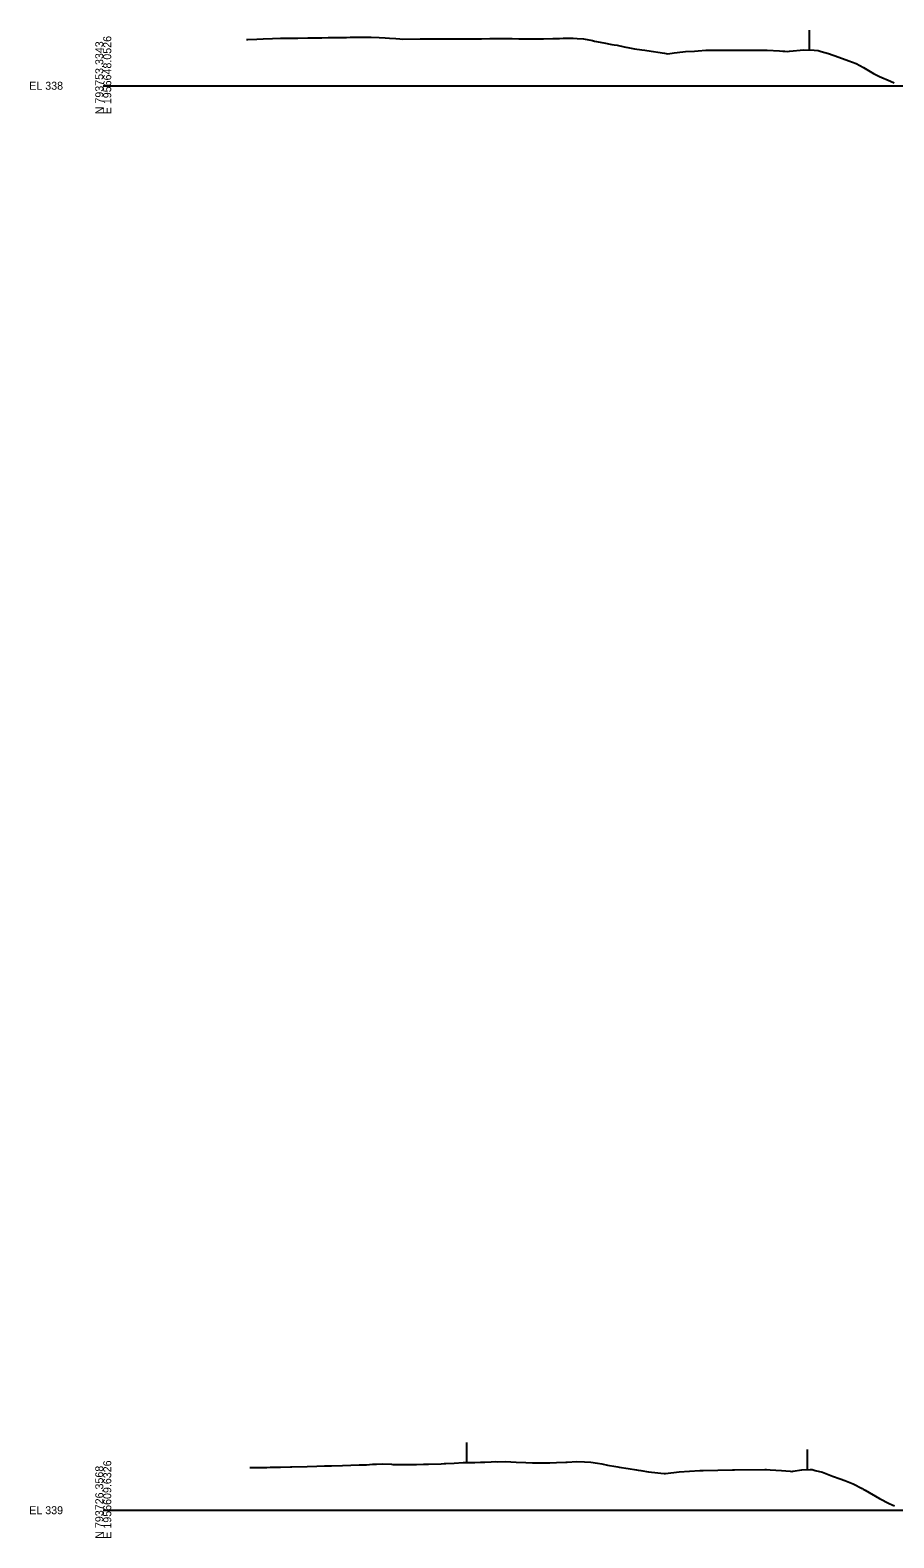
# Model space of a CAD drawing. Extents: x -4026 to 9638, y -10 to 19609.
# Drawn here: x -3026 to -2722, y 1490 to 2020 of the extents above; entities that cross this region are included whole.
import ezdxf

# ---------------------------------------------------------------- set-up
doc = ezdxf.new("R2010")
doc.units = 0
for name, color, linetype in [('Default', 7, 'Continuous'), ('RD_EX_Fence_Other', 7, 'Continuous'), ('RD_GPK_XS_Cell', 7, 'Continuous'), ('RD_XS_ExGround', 7, 'Continuous')]:
    doc.layers.add(name, color=color, linetype=linetype)

msp = doc.modelspace()

# ---------------------------------------------------------------- linework, layer by layer
at = {"layer": 'RD_EX_Fence_Other'}
for p, q in [((-2752.02, 2019.52), (-2752.02, 2012.52)), ((-2872.38, 1523.74), (-2872.38, 1516.74)), ((-2752.74, 1521.26), (-2752.74, 1514.26))]:
    msp.add_line(p, q, dxfattribs=at)
at = {"layer": 'RD_GPK_XS_Cell'}
for p, q in [((-3000, 2000), (-2650, 2000)), ((-3000, 1500), (-2650, 1500))]:
    msp.add_line(p, q, dxfattribs=at)
at = {"layer": 'RD_XS_ExGround'}
for points in [[(-2949.66, 2016.21), (-2949.16, 2016.23), (-2946.07, 2016.39), (-2943.88, 2016.46), (-2940.51, 2016.58), (-2937.76, 2016.65), (-2935.31, 2016.66), (-2931.63, 2016.73), (-2928.14, 2016.77), (-2925.5, 2016.82), (-2924.55, 2016.84), (-2923.22, 2016.87), (-2920.97, 2016.9), (-2919.37, 2016.92), (-2917.38, 2016.94), (-2914.57, 2016.98), (-2913.24, 2017), (-2910.01, 2017.04), (-2907.11, 2017.07), (-2905.92, 2017.05), (-2903.03, 2016.98), (-2900.99, 2016.85), (-2899.45, 2016.76), (-2897.28, 2016.57), (-2895.86, 2016.46), (-2894.86, 2016.41), (-2888.63, 2016.51), (-2885.1, 2016.48), (-2882.6, 2016.47), (-2879.98, 2016.49), (-2876.47, 2016.48), (-2874.34, 2016.49), (-2871.33, 2016.5), (-2870.34, 2016.49), (-2867.17, 2016.48), (-2864.22, 2016.57), (-2863.58, 2016.57), (-2862.69, 2016.58), (-2859.99, 2016.61), (-2858.09, 2016.59), (-2856.41, 2016.57), (-2854.04, 2016.51), (-2852.82, 2016.49), (-2851.96, 2016.5), (-2849.23, 2016.49), (-2845.39, 2016.48), (-2842.06, 2016.53), (-2839.7, 2016.62), (-2838.48, 2016.66), (-2836.74, 2016.67), (-2834.89, 2016.7), (-2833.57, 2016.62), (-2831.3, 2016.46), (-2828.1, 2015.84), (-2827.44, 2015.71), (-2824.13, 2015.04), (-2821.32, 2014.54), (-2820.54, 2014.41), (-2819.45, 2014.19), (-2816.96, 2013.69), (-2815.19, 2013.33), (-2813.37, 2012.99), (-2810.8, 2012.6), (-2809.78, 2012.45), (-2809.06, 2012.35), (-2802.83, 2011.42), (-2801.69, 2011.23), (-2799.43, 2011.5), (-2798.37, 2011.63), (-2795.44, 2011.97), (-2792.35, 2012.16), (-2790.97, 2012.26), (-2788.31, 2012.45), (-2781, 2012.51), (-2777.82, 2012.55), (-2769.03, 2012.54), (-2766.78, 2012.54), (-2762.4, 2012.24), (-2761.25, 2012.15), (-2760.53, 2012.11), (-2759.57, 2012.04), (-2758.92, 2012.12), (-2753.9, 2012.58), (-2750.27, 2012.46), (-2748.81, 2012.36), (-2747.78, 2012.07), (-2745.23, 2011.35), (-2741.63, 2010.01), (-2738.05, 2008.77), (-2735.52, 2007.76), (-2732.98, 2006.38), (-2729.39, 2004.34), (-2727.29, 2003.26), (-2723.43, 2001.58), (-2722.13, 2001.01)], [(-2948.54, 1515.05), (-2946.64, 1515.03), (-2942.53, 1515.05), (-2941.36, 1515.1), (-2940.54, 1515.09), (-2937.77, 1515.14), (-2934.18, 1515.26), (-2933.78, 1515.26), (-2928.36, 1515.38), (-2925.02, 1515.44), (-2922.27, 1515.54), (-2919.81, 1515.63), (-2915.98, 1515.72), (-2910.09, 1515.95), (-2909.03, 1515.97), (-2907.51, 1515.99), (-2905.44, 1516.2), (-2904, 1516.14), (-2901.85, 1516.25), (-2898.76, 1516.14), (-2898.26, 1516.1), (-2897.91, 1516.09), (-2894.66, 1516.09), (-2891.82, 1516.06), (-2891.07, 1516.06), (-2890, 1516.1), (-2887.48, 1516.19), (-2885.73, 1516.19), (-2881.25, 1516.32), (-2880.3, 1516.37), (-2879.64, 1516.4), (-2876.7, 1516.49), (-2873.54, 1516.7), (-2873.11, 1516.71), (-2872.49, 1516.74), (-2869.52, 1516.8), (-2867.45, 1516.88), (-2865.93, 1516.92), (-2863.74, 1516.93), (-2862.34, 1517.05), (-2861.36, 1516.97), (-2858.74, 1517.08), (-2854.98, 1516.82), (-2851.56, 1516.74), (-2849.18, 1516.65), (-2847.97, 1516.64), (-2846.23, 1516.61), (-2844.38, 1516.59), (-2843.09, 1516.61), (-2840.78, 1516.73), (-2837.47, 1516.85), (-2837, 1516.87), (-2833.6, 1517.07), (-2830.91, 1517.04), (-2828.71, 1516.82), (-2826.42, 1516.54), (-2824.82, 1516.23), (-2822.82, 1515.84), (-2819.96, 1515.31), (-2819.23, 1515.18), (-2818.73, 1515.11), (-2815.64, 1514.68), (-2812.64, 1514.13), (-2812.05, 1514.03), (-2811.2, 1513.9), (-2808.46, 1513.47), (-2805.19, 1513.09), (-2804.17, 1512.98), (-2803.01, 1512.84), (-2802.54, 1512.89), (-2797.68, 1513.44), (-2790.42, 1513.9), (-2789.24, 1513.97), (-2778.93, 1514.21), (-2778.6, 1514.22), (-2778.26, 1514.22), (-2767.65, 1514.33), (-2767.05, 1514.29), (-2765.77, 1514.22), (-2761.76, 1514), (-2758.67, 1513.68), (-2758.17, 1513.62), (-2757.82, 1513.67), (-2754.58, 1514.22), (-2751.73, 1514.29), (-2750.98, 1514.27), (-2749.92, 1513.98), (-2747.39, 1513.39), (-2745.64, 1512.7), (-2743.8, 1512), (-2741.16, 1511.06), (-2739.54, 1510.46), (-2736.62, 1509.22), (-2733.45, 1507.68), (-2733.02, 1507.44), (-2732.41, 1507.08), (-2727.36, 1504.07), (-2723.91, 1502.34), (-2722.87, 1501.89), (-2722.09, 1501.54)]]:
    msp.add_lwpolyline(points, dxfattribs=at)

# ---------------------------------------------------------------- texts
at = {"layer": 'Default'}
for p in [(-3000, 2000), (-3000, 1500)]:
    msp.add_text('-', height=0.0001, dxfattribs=at).set_placement(p)
at = {"layer": 'RD_GPK_XS_Cell'}
for s, p in [('E 1956648.0526', (-2997.2, 1990)), ('N 793753.3343', (-3000, 1990)), ('N 793726.3568', (-3000, 1490)), ('E 1956609.6326', (-2997.2, 1490))]:
    msp.add_text(s, height=2.8, rotation=90, dxfattribs=at).set_placement(p)
for s, p in [('EL 338', (-3026, 1998.6)), ('EL 339', (-3026, 1498.6))]:
    msp.add_text(s, height=2.8, dxfattribs=at).set_placement(p)

doc.saveas('drawing.dxf')
